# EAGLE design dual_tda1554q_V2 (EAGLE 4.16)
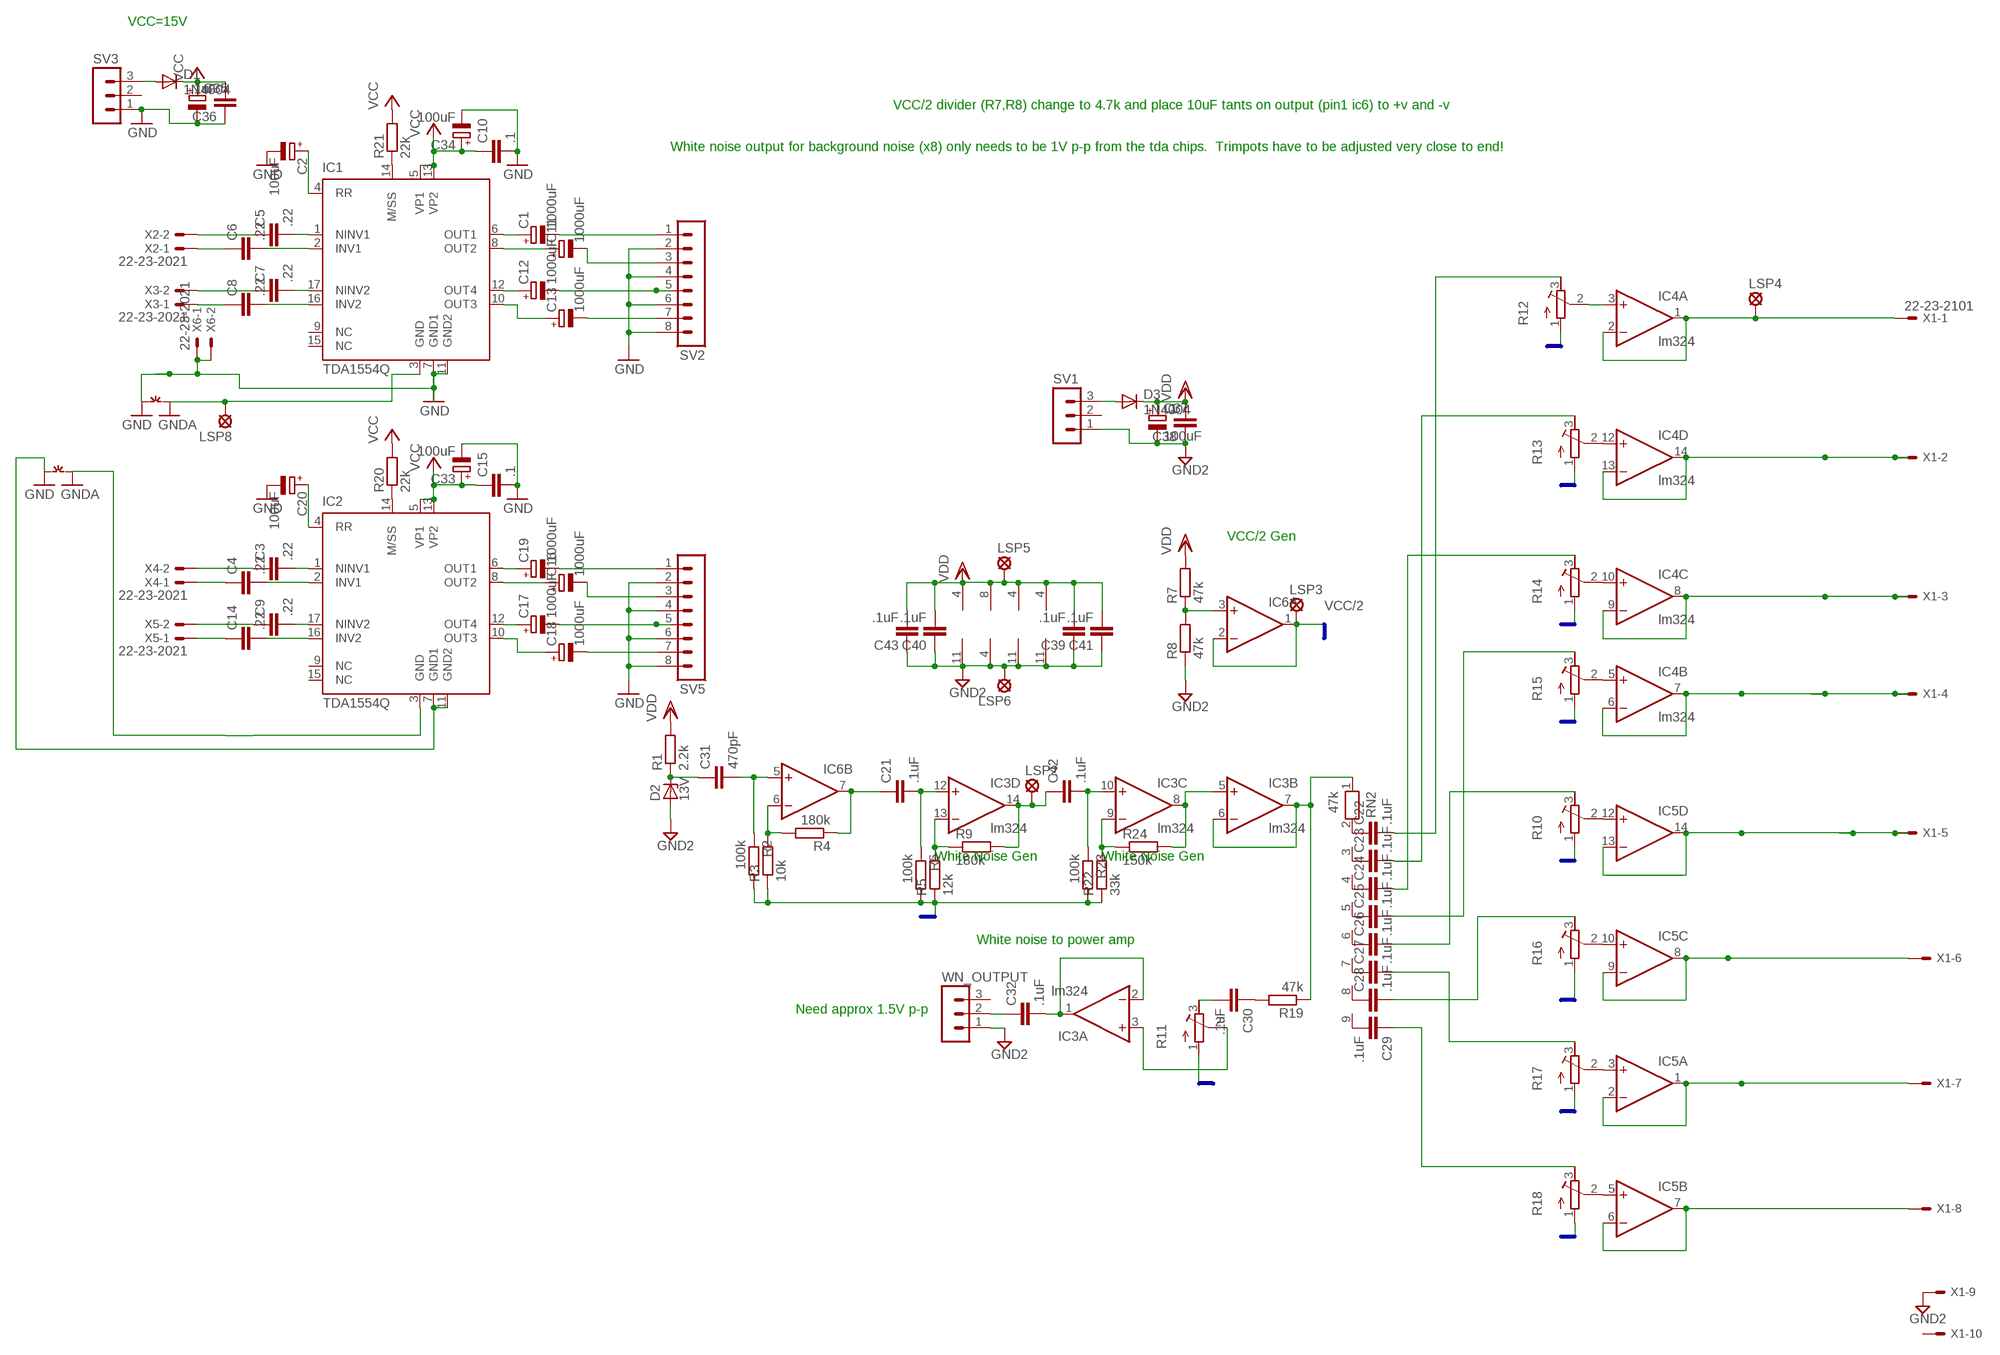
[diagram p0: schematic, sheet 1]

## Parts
C1  1000uF  CPOL-EUE5-10.5  [E5-10,5]
C2  100uF  CPOL-EUE5-6  [E5-6]
C3  .22  C-EU025-025X050  [C025-025X050]
C4  .22  C-EU025-025X050  [C025-025X050]
C5  .22  C-EU025-025X050  [C025-025X050]
C6  .22  C-EU025-025X050  [C025-025X050]
C7  .22  C-EU025-025X050  [C025-025X050]
C8  .22  C-EU025-025X050  [C025-025X050]
C9  .22  C-EU025-025X050  [C025-025X050]
C10  .1  C-EU025-025X050  [C025-025X050]
C11  1000uF  CPOL-EUE5-10.5  [E5-10,5]
C12  1000uF  CPOL-EUE5-10.5  [E5-10,5]
C13  1000uF  CPOL-EUE5-10.5  [E5-10,5]
C14  .22  C-EU025-025X050  [C025-025X050]
C15  .1  C-EU025-025X050  [C025-025X050]
C16  1000uF  CPOL-EUE5-10.5  [E5-10,5]
C17  1000uF  CPOL-EUE5-10.5  [E5-10,5]
C18  1000uF  CPOL-EUE5-10.5  [E5-10,5]
C19  1000uF  CPOL-EUE5-10.5  [E5-10,5]
C20  100uF  CPOL-EUE5-6  [E5-6]
C21  .1uF  C-EU025-025X050  [C025-025X050]
C22  .1uF  C-EU025-025X050  [C025-025X050]
C23  .1uF  C-EU025-025X050  [C025-025X050]
C24  .1uF  C-EU025-025X050  [C025-025X050]
C25  .1uF  C-EU025-025X050  [C025-025X050]
C26  .1uF  C-EU025-025X050  [C025-025X050]
C27  .1uF  C-EU025-025X050  [C025-025X050]
C28  .1uF  C-EU025-025X050  [C025-025X050]
C29  .1uF  C-EU025-025X050  [C025-025X050]
C30  .1uF  C-EU025-025X050  [C025-025X050]
C31  470pF  C-EU025-025X050  [C025-025X050]
C32  .1uF  C-EU025-025X050  [C025-025X050]
C33  100uF  CPOL-EUE5-6  [E5-6]
C34  100uF  CPOL-EUE5-6  [E5-6]
C35  CPOL-EUE7.5-16  [E7,5-16]
C36  .1uF  C-EUC1206  [C1206]
C37  100uF  CPOL-EUE5-8.5  [E5-8,5]
C38  .1  C-EU025-025X050  [C025-025X050]
C39  .1uF  C-EUC1206  [C1206]
C40  .1uF  C-EUC1206  [C1206]
C41  .1uF  C-EUC1206  [C1206]
C42  .1uF  C-EU025-025X050  [C025-025X050]
C43  .1uF  C-EU025-025X050  [C025-025X050]
D1  1N4004  [DO41-10]
D2  13V  ZENER-DIODEF126-10  [F126Z10]
D3  1N4004  [DO41-10]
IC1  TDA1554Q  [MULTIWAT-SIL17]
IC2  TDA1554Q  [MULTIWAT-SIL17]
IC3  lm324  4AMP_P4+11N  [DIL14]
IC4  lm324  4AMP_P4+11N  [DIL14]
IC5  4AMP_P4+11N  [DIL14]
IC6  2AMP_P8+4N  [DIL08]
LSP2  SE14  [SE14]
LSP3  SE14  [SE14]
LSP4  SE14  [SE14]
LSP5  SE14  [SE14]
LSP6  SE14  [SE14]
LSP8  SE14  [SE14]
R1  2.2k  R-EU_0204/2V  [0204V]
R2  100k  R-EU_0204/7  [0204/7]
R3  10k  R-EU_0204/2V  [0204V]
R4  180k  R-EU_0204/2V  [0204V]
R5  12k  R-EU_0204/5  [0204/5]
R6  100k  R-EU_0204/7  [0204/7]
R7  47k  R-EU_0204/2V  [0204V]
R8  47k  R-EU_0204/2V  [0204V]
R9  180k  R-EU_0204/2V  [0204V]
R10  R-TRIMM64Y  [RTRIM64Y]
R11  R-TRIMM64Y  [RTRIM64Y]
R12  R-TRIMM64Y  [RTRIM64Y]
R13  R-TRIMM64Y  [RTRIM64Y]
R14  R-TRIMM64Y  [RTRIM64Y]
R15  R-TRIMM64Y  [RTRIM64Y]
R16  R-TRIMM64Y  [RTRIM64Y]
R17  R-TRIMM64Y  [RTRIM64Y]
R18  R-TRIMM64Y  [RTRIM64Y]
R19  47k  R-EU_0204/2V  [0204V]
R20  22k  R-EU_0204/2V  [0204V]
R21  22k  R-EU_0204/2V  [0204V]
R22  33k  R-EU_0204/7  [0204/7]
R23  100k  R-EU_0204/5  [0204/5]
R24  150k  R-EU_0204/2V  [0204V]
RN2  47k  RN08  [RN-9]
SV1  MA03-1  [MA03-1]
SV2  MA08-1  [MA08-1]
SV3  MA03-1  [MA03-1]
SV5  MA08-1  [MA08-1]
WN_OUTPUT  MA03-1  [MA03-1]
X1  22-23-2101  [22-23-2101]
X2  22-23-2021  [22-23-2021]
X3  22-23-2021  [22-23-2021]
X4  22-23-2021  [22-23-2021]
X5  22-23-2021  [22-23-2021]
X6  22-23-2021  [22-23-2021]
~NUDEV~1  GND-GNDA  [GND-GNDA]
~NUDEV~2  GND-GNDA  [GND-GNDA]

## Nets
A1 [AF_OUT]: C1.- SV2.1
A2 [AF_OUT]: C11.- SV2.3
A3 [AF_OUT]: C12.- SV2.5
A4 [AF_OUT]: C13.- SV2.7
A5 [AF_OUT]: C19.- SV5.1
A6 [AF_OUT]: C16.- SV5.3
A7 [AF_OUT]: C17.- SV5.5
A8 [AF_OUT]: C18.- SV5.7
GND [power]: C2.- C10.2 C15.2 C20.- C33.- C34.- C35.- C36.1 IC1.7(GND1) IC1.11(GND2) IC2.7(GND1) IC2.11(GND2) SV2.2 SV2.4 SV2.6 SV2.8 SV3.1 SV5.2 SV5.4 SV5.6 SV5.8 X6.1 X6.2 ~NUDEV~1.GND ~NUDEV~2.GND
GND2 [power]: C37.- C38.1 C39.1 C40.1 C41.1 C43.1 D2.A IC3.11(P:V-) IC4.11(P:V-) IC5.11(P:V-) IC6.4(P:V-) LSP6.MP R8.1 SV1.1 WN_OUTPUT.1 X1.9
GNDA [SIG_GND]: IC1.3(GND) IC2.3(GND) LSP8.MP ~NUDEV~1.GNDA ~NUDEV~2.GNDA
INV1: C6.2 IC1.2(INV1)
INV2: C8.2 IC1.16(INV2)
INV3: C14.2 IC2.16(INV2)
N$1 [AF_OUT]: C13.+ IC1.10(OUT3)
N$2: IC2.14(M/SS) R20.1
N$3 [AF_OUT]: C12.+ IC1.12(OUT4)
N$4: IC1.14(M/SS) R21.1
N$5 [AF_OUT]: C11.+ IC1.8(OUT2)
N$6 [power]: D3.A SV1.3
N$7: C3.2 IC2.1(NINV1)
N$8: C2.+ IC1.4(RR)
N$9 [AF_OUT]: C1.+ IC1.6(OUT1)
N$10: C27.2 R17.3(A)
N$11: C31.2 IC6.5(B:+IN) R2.1
N$12 [SIG_GND]: C3.1 X4.2
N$13: C9.1 X5.2
N$14 [power]: D1.A SV3.3
N$15: C14.1 X5.1
N$16: C5.1 X2.2
N$17: C6.1 X2.1
N$18: C7.1 X3.2
N$19 [AF_OUT]: C18.+ IC2.10(OUT3)
N$20: C8.1 X3.1
N$21 [AF_OUT]: C17.+ IC2.12(OUT4)
N$22 [AF_OUT]: C16.+ IC2.8(OUT2)
N$23: C42.1 IC3.14(D:OUT) LSP2.MP R9.2
N$24: C42.2 IC3.10(C:+IN) R23.1
N$25: C20.+ IC2.4(RR)
N$26 [AF_OUT]: C19.+ IC2.6(OUT1)
N$27: IC3.9(C:-IN) R22.2 R24.1
N$28: C31.1 D2.C R1.1
N$29: IC6.6(B:-IN) R3.2 R4.2
N$30: IC6.3(A:+IN) R7.1 R8.2
N$31: C21.2 IC3.12(D:+IN) R6.1
N$32: C29.2 RN2.9
N$33: IC3.13(D:-IN) R5.2 R9.1
N$34: C29.1 R18.3(A)
N$35: C21.1 IC6.7(B:OUT) R4.1
N$36: C30.1 R19.2
N$37: C28.2 R16.3(A)
N$38: C26.2 R10.3(A)
N$39: C25.2 R15.3(A)
N$40: C24.2 R14.3(A)
N$41: C23.2 R13.3(A)
N$42: C22.2 R12.3(A)
N$43: C22.1 RN2.2
N$44: C23.1 RN2.3
N$45: C24.1 RN2.4
N$46: C25.1 RN2.5
N$47: C26.1 RN2.6
N$48: C32.1 WN_OUTPUT.2
N$49: IC4.3(A:+IN) R12.2(S)
N$50: C27.1 RN2.7
N$51: IC5.12(D:+IN) R10.2(S)
N$52: IC5.10(C:+IN) R16.2(S)
N$53: IC4.12(D:+IN) R13.2(S)
N$54: C28.1 RN2.8
N$55: IC4.10(C:+IN) R14.2(S)
N$56: C4.2 IC2.2(INV1)
N$57 [SIG_GND]: C4.1 X4.1
N$58: IC5.3(A:+IN) R17.2(S)
N$59: IC5.5(B:+IN) R18.2(S)
N$60: IC3.5(B:+IN) IC3.8(C:OUT) R24.2
N$61: C30.2 R11.3(A)
N$62: IC3.6(B:-IN) IC3.7(B:OUT) R19.1 RN2.1
N$72: IC4.5(B:+IN) R15.2(S)
NINV1: C5.2 IC1.1(NINV1)
NINV2: C7.2 IC1.17(NINV2)
NINV3: C9.2 IC2.17(NINV2)
VCC [power]: C10.1 C15.1 C33.+ C34.+ C35.+ C36.2 D1.C IC1.5(VP1) IC1.13(VP2) IC2.5(VP1) IC2.13(VP2) R20.2 R21.2
VCC/2 [vcc/2]: IC6.1(A:OUT) IC6.2(A:-IN) LSP3.MP R2.2 R3.1 R5.1 R6.2 R10.1(E) R11.1(E) R12.1(E) R13.1(E) R14.1(E) R15.1(E) R16.1(E) R17.1(E) R18.1(E) R22.1 R23.2
VDD [power]: C37.+ C38.2 C39.2 C40.2 C41.2 C43.2 D3.C IC3.4(P:V+) IC4.4(P:V+) IC5.4(P:V+) IC6.8(P:V+) LSP5.MP R1.2 R7.2
WN1: IC4.1(A:OUT) IC4.2(A:-IN) LSP4.MP X1.1
WN2: IC4.13(D:-IN) IC4.14(D:OUT) X1.2
WN3: IC4.8(C:OUT) IC4.9(C:-IN) X1.3
WN4: IC4.6(B:-IN) IC4.7(B:OUT) X1.4
WN5: IC5.13(D:-IN) IC5.14(D:OUT) X1.5
WN6: IC5.1(A:OUT) IC5.2(A:-IN) X1.7
WN7: IC5.8(C:OUT) IC5.9(C:-IN) X1.6
WN8: IC5.6(B:-IN) IC5.7(B:OUT) X1.8
WN+: IC3.3(A:+IN) R11.2(S)
WN_FEEDBACK: C32.2 IC3.1(A:OUT) IC3.2(A:-IN)
Unconnected: IC1.9(NC) IC1.15(NC) IC2.9(NC) IC2.15(NC) SV1.2 SV3.2 WN_OUTPUT.3 X1.10

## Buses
VCC/2

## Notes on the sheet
- VCC=15V
- VCC/2 divider (R7,R8) change to 4.7k and place 10uF tants on output (pin1 ic6) to +v and -v
- White noise output for background noise (x8) only needs to be 1V p-p from the tda chips.  Trimpots have to be adjusted very close to end!
- VCC/2 Gen
- White Noise Gen | White Noise Gen
- White noise to power amp
- Need approx 1.5V p-p

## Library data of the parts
C1 C2 C11-C13 C16-C20 C33-C35 C37 = rcl:CPOL-EU: POLARIZED CAPACITOR, European symbol
C3-C10 C14 C15 C21-C32 C36 C38-C43 = rcl:C-EU: CAPACITOR, European symbol
D1 D3 = diode:1N4004: DIODE
D2 = diode:ZENER-DIODE: Z-Diode
IC1 IC2 = linear2:TDA1554Q: Audio Power Amplifier 4x11W single-ended or 2x22W BTL source: TDA1554Q_CNV.pdf
IC3-IC5 = linear:4AMP_P4+11: OP AMP
IC6 = linear:2AMP_P8+4: OP AMP
LSP2-LSP6 LSP8 = solpad:SE14: SOLDER PAD
R1-R9 R19-R24 = rcl:R-EU_: RESISTOR, European symbol
R10-R18 = rcl:R-TRIMM: Trimm resistor
RN2 = resistor-net:RN08: RESISTOR NETWORK
SV1 SV3 WN_OUTPUT = con-lstb:MA03-1: PIN HEADER
SV2 SV5 = con-lstb:MA08-1: PIN HEADER
X1 = con-molex:22-23-2101: .100" (2.54mm) Center Header - 10 Pin
X2-X6 = con-molex:22-23-2021: .100" (2.54mm) Center Header - 2 Pin
~NUDEV~1 ~NUDEV~2 = supply-dummy:GND-GNDA: Example of GND--GNDA NET-Connetor for more info read description in package

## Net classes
0 default: width 0.254 mm, drill 0.254 mm, clearance 0.711 mm
1 power: width 1.016 mm, drill 0.61 mm, clearance 0.711 mm
2 vcc/2: width 0.508 mm, drill 0.254 mm, clearance 0.711 mm
3 AF_OUT: width 0.508 mm, drill 0.254 mm, clearance 0.711 mm
4 SIG_GND: width 0.508 mm, drill 0.254 mm, clearance 0.711 mm

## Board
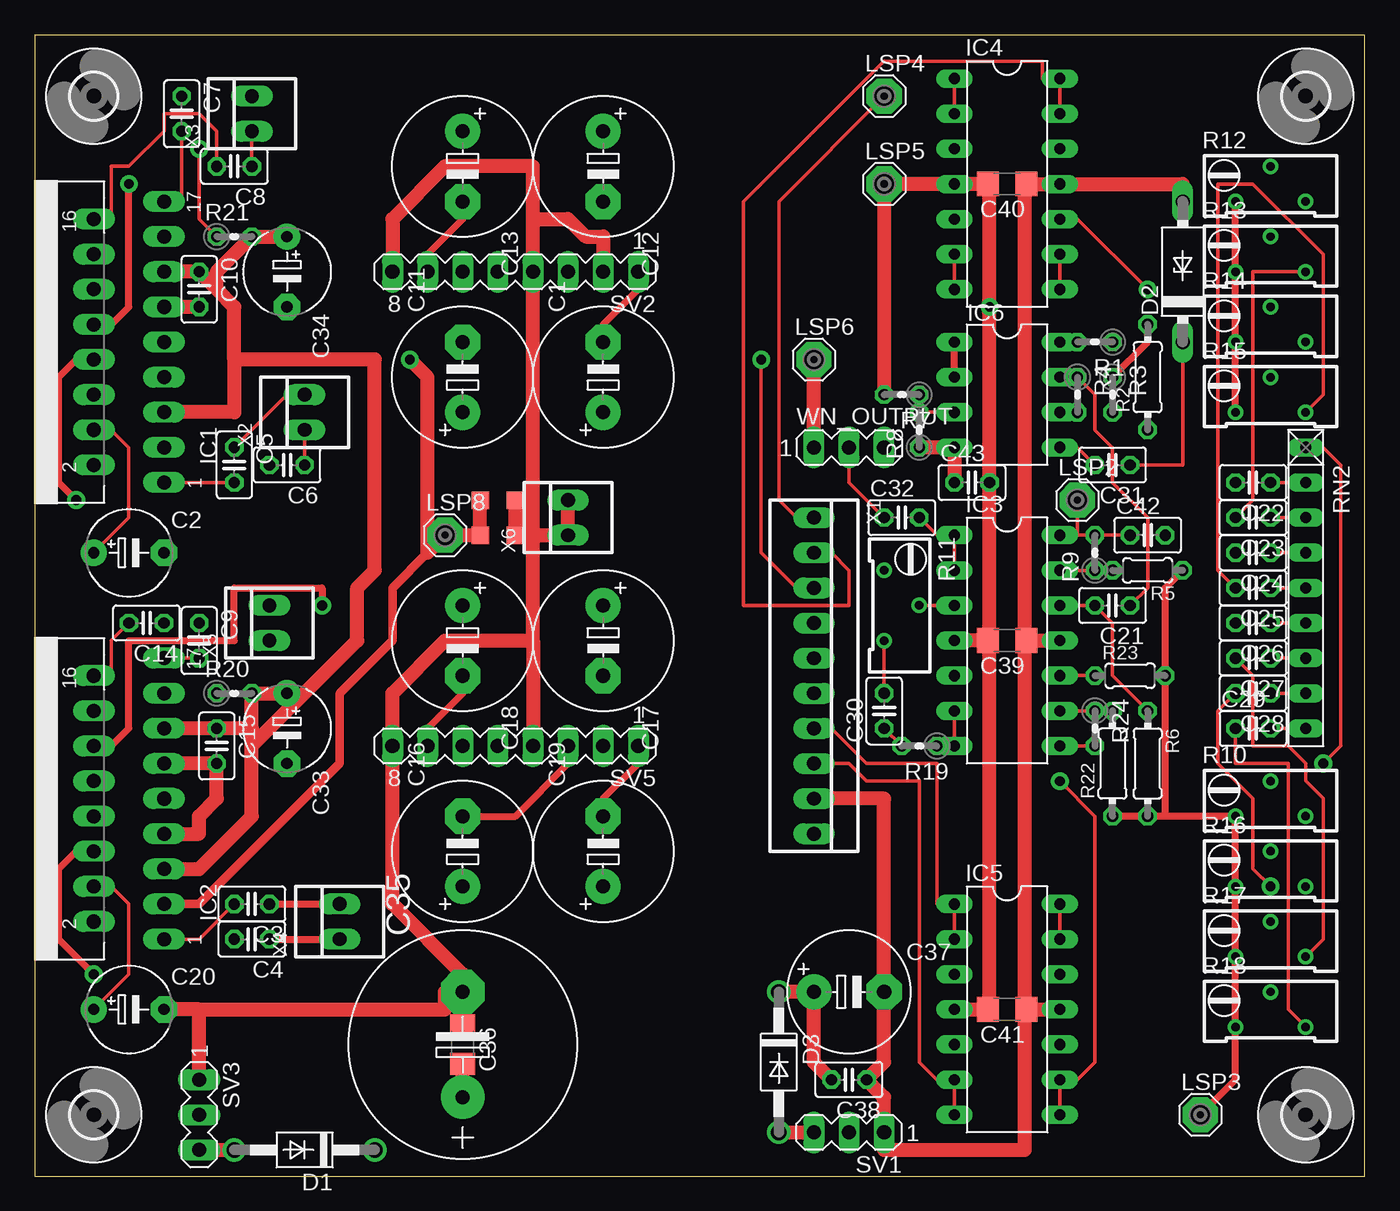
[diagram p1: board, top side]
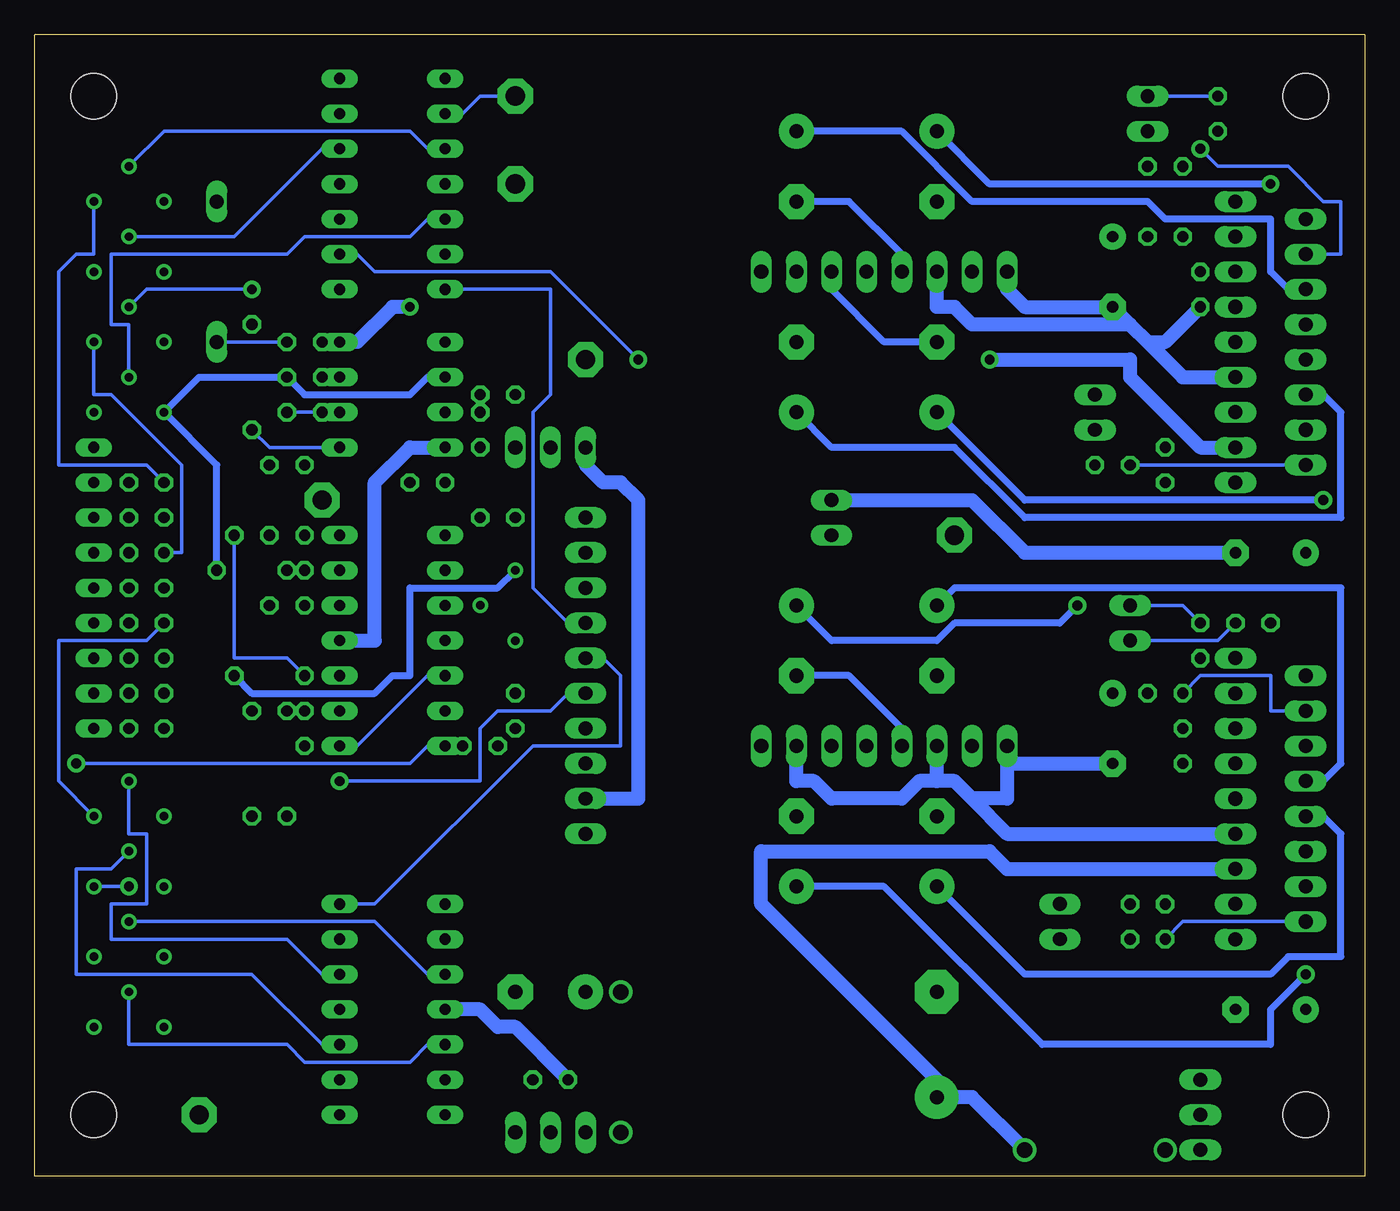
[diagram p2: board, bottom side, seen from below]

Size 96.19 x 82.55 mm. Coordinates in mm from the lower left corner, seen from the top.
Outline: 96.19,82.54 96.19,0 0,0 0,82.54
Outline: 0,82.55 96.19,82.55
Copper layers (1*16): Top 0.035mm / dielectric 1.5mm / Bottom 0.035mm
Design rules "futurlec": minimum track width 10mil, minimum drill 24mil, track to track 10mil, track to pad 10mil, pad to pad 10mil, via to via 10mil, smd to smd 0mil, copper to edge 40mil, drill to drill 10mil, minimum pad ring 10mil, minimum via ring 8mil, stop-mask expansion 4mil, vias tented up to drill 0mil, thermal gap 10mil
tRestrict: area 18.2,76.8 to 19.5,79.4; area 20.8,54 to 22.1,56.5; area 18.2,38.7 to 19.5,41.3; area 15.7,36.2 to 18.2,37.5; area 23.3,17.1 to 24.6,19.7; area 46.2,1.9 to 50,80.6
bRestrict: area 18.2,38.7 to 19.5,41.3; area 20.8,54 to 22.1,56.5; area 18.2,76.8 to 19.5,79.4; area 15.7,36.2 to 18.2,37.5; area 23.3,17.1 to 24.6,19.7; area 46.2,1.9 to 50,80.6

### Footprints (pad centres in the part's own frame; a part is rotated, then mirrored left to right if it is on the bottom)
E5-10,5 = drill 1.016 pad 2.54 round: + -2.54,0 | drill 1.016 pad 2.54 octagon: - 2.54,0
E5-6 = drill 0.813 pad 1.905 round: + -2.54,0 | drill 0.813 pad 1.905 octagon: - 2.54,0
C025-025X050 = drill 0.813 octagon: 1 -1.27,0; 2 1.27,0
E7,5-16 = drill 1.016 pad 3.15 round: + -3.81,0 | drill 1.016 pad 3.15 octagon: - 3.81,0
C1206 = smd 1.6 x 1.8: 1 -1.4,0; 2 1.4,0
E5-8,5 = drill 1.016 pad 2.54 round: + -2.54,0 | drill 1.016 pad 2.54 octagon: - 2.54,0
DO41-10 = drill 1.118 round: A 5.08,0; C -5.08,0
F126Z10 = drill 1.016 long: A 5.08,0; C -5.08,0
MULTIWAT-SIL17 = drill 1.016 long: 1 -10.16,-7.62; 2 -8.89,-2.54; 3 -7.62,-7.62; 4 -6.35,-2.54; 5 -5.08,-7.62; 6 -3.81,-2.54; 7 -2.54,-7.62; 8 -1.27,-2.54; 9 0,-7.62; 10 1.27,-2.54; 11 2.54,-7.62; 12 3.81,-2.54; 13 5.08,-7.62; 14 6.35,-2.54; 15 7.62,-7.62; 16 8.89,-2.54; 17 10.16,-7.62
DIL14 = drill 0.813 long: 1 -7.62,-3.81; 2 -5.08,-3.81; 3 -2.54,-3.81; 4 0,-3.81; 5 2.54,-3.81; 6 5.08,-3.81; 7 7.62,-3.81; 8 7.62,3.81; 9 5.08,3.81; 10 2.54,3.81; 11 0,3.81; 12 -2.54,3.81; 13 -5.08,3.81; 14 -7.62,3.81
DIL08 = drill 0.813 long: 1 -3.81,-3.81; 2 -1.27,-3.81; 3 1.27,-3.81; 4 3.81,-3.81; 5 3.81,3.81; 6 1.27,3.81; 7 -1.27,3.81; 8 -3.81,3.81
SE14 = drill 1.397 pad 2.54 octagon: MP 0,0
0204V = drill 0.813 octagon: 1 -1.27,0; 2 1.27,0
0204/7 = drill 0.813 octagon: 1 -3.81,0; 2 3.81,0
0204/5 = drill 0.813 octagon: 1 -2.54,0; 2 2.54,0
RTRIM64Y = drill 0.61 round: 1 0,-2.54; 2 -2.54,0; 3 0,2.54
RN-9 = drill 0.813 long: 1 -10.16,0; 2 -7.62,0; 3 -5.08,0; 4 -2.54,0; 5 0,0; 6 2.54,0; 7 5.08,0; 8 7.62,0; 9 10.16,0
MA03-1 = drill 1.016 long: 1 -2.54,0; 2 0,0; 3 2.54,0
MA08-1 = drill 1.016 long: 1 -8.89,0; 2 -6.35,0; 3 -3.81,0; 4 -1.27,0; 5 1.27,0; 6 3.81,0; 7 6.35,0; 8 8.89,0
3,3 = hole 3.3: 0,0
22-23-2101 = drill 1 long: 1 -11.43,0; 2 -8.89,0; 3 -6.35,0; 4 -3.81,0; 5 -1.27,0; 6 1.27,0; 7 3.81,0; 8 6.35,0; 9 8.89,0; 10 11.43,0
22-23-2021 = drill 1 long: 1 -1.27,0; 2 1.27,0
GND-GNDA = smd 1.27 x 1.27: GND -1.27,0; GNDA 1.27,0

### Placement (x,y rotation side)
C1  41.11,57.78 90 top
C2  6.82,45.08 0 top
C3  15.71,19.68 180 top
C4  15.71,17.14 180 top
C5  14.44,51.43 270 top
C6  18.25,51.43 180 top
C7  10.63,76.83 270 top
C8  14.44,73.02 180 top
C9  11.9,38.73 270 top
C10  11.9,64.13 270 top
C11  30.95,57.78 90 top
C12  41.11,73.02 270 top
C13  30.95,73.02 270 top
C14  8.09,40 180 top
C15  13.17,31.11 270 top
C16  30.95,23.49 90 top
C17  41.11,38.73 270 top
C18  30.95,38.73 270 top
C19  41.11,23.49 90 top
C20  6.82,12.06 0 top
C21  77.94,41.27 180 top
C22  88.1,50.16 180 top
C23  88.1,47.62 180 top
C24  88.1,45.08 180 top
C25  88.1,42.54 180 top
C26  88.1,40 180 top
C27  88.1,37.46 180 top
C28  88.1,34.92 180 top
C29  88.1,32.38 0 top
C30  61.43,33.65 90 top
C31  77.94,51.43 180 top
C32  62.7,47.62 0 top
C33  18.25,32.38 270 top
C34  18.25,65.4 270 top
C35  30.95,9.52 90 top
C36  30.95,9.52 270 top
C37  58.89,13.33 0 top
C38  58.89,6.98 180 top
C39  70.32,38.73 180 top
C40  70.32,71.75 180 top
C41  70.32,12.06 180 top
C42  80.48,46.35 0 top
C43  67.78,50.16 0 top
D1  19.52,1.9 180 top
D2  83.02,65.4 90 top
D3  53.81,8.25 270 top
IC1  1.74,60.32 90 top
IC2  1.74,27.3 90 top
IC3  70.32,38.73 270 top
IC4  70.32,71.75 270 top
IC5  70.32,12.06 270 top
IC6  70.32,56.51 270 top
LSP2  75.4,48.89 0 top
LSP3  84.29,4.44 0 top
LSP4  61.43,78.1 0 top
LSP5  61.43,71.75 0 top
LSP6  56.35,59.05 0 top
LSP8  29.68,46.35 0 top
R1  76.67,60.32 180 top
R2  80.48,57.78 90 top
R3  77.94,56.51 270 top
R4  75.4,56.51 270 top
R5  80.48,43.81 180 top
R6  80.48,29.84 270 top
R7  62.7,56.51 180 top
R8  63.97,53.97 90 top
R9  76.67,45.08 90 top
R10  89.37,26.03 270 top
R11  61.43,41.27 180 top
R12  89.37,70.48 270 top
R13  89.37,65.4 270 top
R14  89.37,60.32 270 top
R15  89.37,55.24 270 top
R16  89.37,20.95 270 top
R17  89.37,15.87 270 top
R18  89.37,10.79 270 top
R19  63.97,31.11 180 top
R20  14.44,34.92 0 top
R21  14.44,67.94 0 top
R22  77.94,29.84 90 top
R23  79.21,36.19 0 top
R24  76.67,32.38 270 top
RN2  91.91,42.54 270 top
SV1  58.89,3.17 180 top
SV2  34.76,65.4 180 top
SV3  11.9,4.44 270 top
SV5  34.76,31.11 180 top
U$1  [3,3]  4.28,78.1 0 top
U$2  [3,3]  91.91,78.1 0 top
U$3  [3,3]  91.91,4.44 0 top
U$4  [3,3]  4.28,4.44 0 top
WN_OUTPUT  58.89,52.7 0 top
X1  56.35,36.19 270 top
X2  19.52,55.24 90 top
X3  15.71,76.83 90 top
X4  22.06,18.41 90 top
X5  16.98,40 90 top
X6  38.57,47.62 90 top
~NUDEV~1  33.49,46.35 180 top
~NUDEV~2  33.49,48.89 180 top

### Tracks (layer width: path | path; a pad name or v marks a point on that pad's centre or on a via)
A1
  Top 0.508: C1.- 41.11,61.59 43.65,64.13 SV2.1
A2
  Bottom 0.508: C11.- 34.76,60.32 38.57,64.13 SV2.3
A3
  Bottom 0.508: C12.- 37.3,70.48 33.49,66.67 SV2.5
A4
  Top 0.508: C13.- 30.95,69.21 28.41,66.67 SV2.7
A5
  Top 0.508: C19.- 41.11,27.3 43.65,29.84 SV5.1
A6
  Top 0.508: C16.- 34.76,26.03 38.57,29.84 SV5.3
A7
  Bottom 0.508: C17.- 37.3,36.19 33.49,32.38 SV5.5
A8
  Top 0.508: C18.- 30.95,34.92 28.41,32.38 SV5.7
GND
  Top 1.016: 30.95,10.79 C36.1 C35.- | 11.9,12.06 C20.- | 11.9,12.06 29.68,12.06 29.68,13.33 C35.- | IC2.11 C15.2 13.17,27.3 11.9,26.03 11.9,24.76 IC2.7 | C35.- 30.95,14.6 25.87,19.68 SV5.8 25.87,34.92 29.68,38.73 36.03,38.73 | C10.2 IC1.11 | ~NUDEV~2.GND ~NUDEV~1.GND 36.03,46.35 | 36.03,46.35 X6.1 X6.2 | 36.03,38.73 36.03,46.35 | 36.03,38.73 SV5.4 | 36.03,46.35 SV2.4 36.03,69.21 | 36.03,69.21 38.57,69.21 39.84,67.94 41.11,67.94 SV2.2 | 36.03,69.21 36.03,73.02 29.68,73.02 25.87,69.21 SV2.8 | SV3.1 11.9,12.06
  Bottom 1.016: 25.87,29.84 C33.- | 30.95,28.57 29.68,28.57 28.41,27.3 | 28.41,27.3 25.87,24.76 IC2.7 | 30.95,28.57 SV5.6 | 30.95,28.57 32.22,28.57 33.49,27.3 38.57,27.3 39.84,28.57 41.11,28.57 SV5.2 | 25.87,29.84 25.87,27.3 28.41,27.3 | SV5.8 25.87,29.84 | 16.98,61.59 C34.- 24.6,62.86 25.87,64.13 SV2.8 | 16.98,61.59 15.71,60.32 | 15.71,60.32 13.17,57.78 IC1.7 | C10.2 14.44,60.32 15.71,60.32 | C2.- 24.6,45.08 28.41,48.89 X6.2 | 16.98,61.59 28.41,61.59 29.68,62.86 30.95,62.86 SV2.6
GND2
  Top 1.016: WN_OUTPUT.1 LSP6.MP | X1.9 61.43,27.3 C37.- 61.43,8.25 C38.1 61.43,5.71 SV1.1 61.43,1.9 71.59,1.9 71.59,12.06 | D2.A 83.02,71.75 IC4.11 C40.1 71.59,71.75 71.59,38.73 | C43.1 IC6.4 R8.1 | IC5.11 C41.1 71.59,12.06 | IC3.11 C39.1 71.59,38.73 | 71.59,12.06 71.59,38.73
  Bottom 1.016: WN_OUTPUT.1 56.35,51.43 55.08,50.16 53.81,50.16 52.54,48.89 52.54,27.3 X1.9 | IC6.4 69.05,52.7 71.59,50.16 71.59,38.73 IC3.11
GNDA  (via drill 0.71)
  Top 0.61: 28.41,45.08 25.87,42.54 25.87,38.73 22.06,34.92 22.06,29.84 11.9,19.68 IC2.3
  Top 1.016: ~NUDEV~2.GNDA ~NUDEV~1.GNDA LSP8.MP 28.41,45.08 28.41,57.78 v27.14,59.05
  Bottom 1.016: v27.14,59.05 16.98,59.05 16.98,57.78 11.9,52.7 IC1.3
INV1
  Bottom 0.254: IC1.2 C6.2
INV2
  Top 0.254: C8.2 13.17,75.56 11.9,76.83 9.36,76.83 9.36,75.56 6.82,73.02 5.55,73.02 5.55,69.21 IC1.16
INV3
  Top 0.254: C14.2 5.55,38.73 5.55,36.19 IC2.16
N$1  (via drill 0.71)
  Top 0.508: v6.82,71.75 6.82,62.86 5.55,61.59 IC1.10
  Bottom 0.508: v6.82,71.75 27.14,71.75 C13.+
N$2
  Bottom 0.254: R20.1 11.9,36.19 6.82,36.19 6.82,33.65 IC2.14
N$3
  Bottom 0.508: C12.+ 33.49,75.56 28.41,70.48 15.71,70.48 14.44,69.21 6.82,69.21 6.82,65.4 5.55,64.13 IC1.12
N$4  (via drill 0.71)
  Top 0.254: R21.1 11.9,69.21 v11.9,74.29
  Bottom 0.254: v11.9,74.29 10.63,73.02 5.55,73.02 3.01,70.48 1.74,70.48 1.74,66.67 IC1.14
N$5  (via drill 0.71)
  Top 0.508: v3.01,48.89 1.74,50.16 1.74,57.78 3.01,59.05 IC1.8
  Bottom 0.508: v3.01,48.89 24.6,48.89 C11.+
N$6
  Top 1.016: D3.A SV1.3
N$7
  Top 0.254: C3.2 11.9,17.14 IC2.1
N$8
  Top 0.254: C2.+ 6.82,47.62 6.82,52.7 5.55,53.97 IC1.4
N$9
  Bottom 0.508: C1.+ 38.57,52.7 29.68,52.7 24.6,47.62 1.74,47.62 1.74,55.24 3.01,56.51 IC1.6
N$10
  Top 0.254: R17.3 93.18,17.14 93.18,27.3 91.91,28.57 91.91,29.84 90.64,31.11 88.1,31.11 88.1,36.19 C27.2
N$11
  Top 0.254: C31.2 75.4,52.7 IC6.5
  Bottom 0.254: R2.1 79.21,52.7 IC6.5
N$12
  Top 0.508: C3.1 X4.2
N$13
  Bottom 0.254: C9.1 13.17,41.27 X5.2
N$14
  Top 1.016: SV3.3 D1.A
N$15
  Bottom 0.254: C14.1 10.63,38.73 X5.1
N$16
  Top 0.254: C5.1 18.25,56.51 X2.2
N$17
  Top 0.254: C6.1 X2.1
N$18
  Bottom 0.254: C7.1 X3.2
N$19
  Bottom 0.508: C18.+ 29.68,42.54 1.74,42.54 1.74,29.84 3.01,28.57 IC2.10
N$20
  Top 0.254: C8.1 X3.1
N$21  (via drill 0.71)
  Top 0.508: v20.79,41.27 20.79,42.54 14.44,42.54 14.44,38.73 6.82,38.73 6.82,32.38 5.55,31.11 IC2.12
  Bottom 0.508: v20.79,41.27 22.06,40 29.68,40 30.95,38.73 38.57,38.73 C17.+
N$22
  Bottom 0.508: C16.+ 24.6,14.6 6.82,14.6 5.55,15.87 1.74,15.87 1.74,24.76 3.01,26.03 IC2.8
N$23
  Top 0.254: 75.4,46.35 R9.2 C42.1 | 75.4,46.35 LSP2.MP | IC3.14 75.4,46.35
N$24
  Top 0.254: IC3.10 R23.1
  Bottom 0.254: C42.2 81.75,37.46 77.94,37.46 R23.1
N$25
  Top 0.254: C20.+ 6.82,14.6 6.82,19.68 5.55,20.95 IC2.4
N$26  (via drill 0.71)
  Top 0.508: v4.28,14.6 1.74,17.14 1.74,22.22 3.01,23.49 IC2.6
  Bottom 0.508: v4.28,14.6 6.82,12.06 6.82,9.52 23.33,9.52 34.76,20.95 C19.+
N$27
  Top 0.254: IC3.9 R24.1 R22.2
N$28
  Top 0.254: C31.1 83.02,51.43 D2.C
  Bottom 0.254: D2.C R1.1
N$29
  Top 0.254: IC6.6 R4.2
  Bottom 0.254: R3.2 R4.2 IC6.6
N$30
  Top 0.254: R7.1 R8.2 IC6.3
N$31
  Top 0.254: IC3.12 C21.2 77.94,40 77.94,36.19 R6.1
N$32
  Top 0.254: C29.2 RN2.9
N$33
  Top 0.254: IC3.13 R9.1 R5.2
N$34
  Top 0.254: R18.3 90.64,12.06 90.64,29.84 86.83,29.84 C29.1
N$35
  Top 0.254: R4.1 IC6.7 R4.1 | C21.1 80.48,42.54 80.48,47.62 77.94,50.16 77.94,52.7 76.67,53.97 76.67,56.51 R4.1
N$36
  Top 0.254: R19.2 C30.1
N$37  (via drill 0.71)
  Top 0.254: v89.37,20.95 88.1,22.22 88.1,27.3 85.56,29.84 85.56,33.65 C28.2
  Bottom 0.254: v89.37,20.95 R16.3
N$38
  Bottom 0.254: R10.3 94.45,28.57 94.45,38.73 88.1,38.73 C26.2
N$39
  Top 0.254: R15.3 93.18,56.51 93.18,66.67 88.1,71.75 85.56,71.75 85.56,43.81 C25.2
N$40
  Bottom 0.254: R14.3 91.91,56.51 90.64,56.51 85.56,51.43 85.56,45.08 C24.2
N$41
  Top 0.254: R13.3 88.1,65.4 88.1,48.89 C23.2
N$42
  Bottom 0.254: R12.3 91.91,66.67 93.18,66.67 94.45,65.4 94.45,51.43 88.1,51.43 C22.2
N$43
  Top 0.254: C22.1 RN2.2
N$44
  Top 0.254: C23.1 RN2.3
N$45
  Top 0.254: C24.1 RN2.4
N$46
  Top 0.254: C25.1 RN2.5
N$47
  Top 0.254: C26.1 RN2.6
N$48
  Top 0.254: C32.1 58.89,50.16 WN_OUTPUT.2
N$49
  Bottom 0.254: R12.2 86.83,75.56 69.05,75.56 67.78,74.29 IC4.3
N$50
  Top 0.254: C27.1 RN2.7
N$51
  Bottom 0.254: R10.2 89.37,24.76 88.1,24.76 88.1,19.68 90.64,19.68 90.64,17.14 77.94,17.14 75.4,14.6 IC5.12
N$52
  Bottom 0.254: R16.2 90.64,22.22 93.18,22.22 93.18,14.6 80.48,14.6 75.4,9.52 IC5.10
N$53
  Bottom 0.254: R13.2 81.75,67.94 75.4,74.29 IC4.12
N$54
  Top 0.254: C28.1 RN2.8
N$55  (via drill 0.71)
  Top 0.254: v80.48,64.13 75.4,69.21 IC4.10
  Bottom 0.254: R14.2 88.1,64.13 v80.48,64.13
N$56
  Bottom 0.254: C4.2 13.17,18.41 IC2.2
N$57
  Top 0.508: C4.1 X4.1
N$58
  Bottom 0.254: R17.2 71.59,18.41 67.78,14.6 IC5.3
N$59
  Bottom 0.254: R18.2 89.37,9.52 77.94,9.52 76.67,8.25 69.05,8.25 67.78,9.52 IC5.5
N$60
  Top 0.254: IC3.8 R24.2
  Bottom 0.254: IC3.5 67.78,36.19 72.86,31.11 IC3.8
N$61
  Top 0.254: C30.2 R11.3
N$62  (via drill 0.71)
  Top 0.254: R19.1 IC3.7 IC3.6 | v93.18,29.84 94.45,31.11 94.45,51.43 93.18,52.7 RN2.1
  Bottom 0.254: v93.18,29.84 69.05,29.84 67.78,31.11 IC3.7
N$72
  Bottom 0.254: R15.2 89.37,61.59 90.64,61.59 90.64,66.67 77.94,66.67 76.67,67.94 69.05,67.94 67.78,69.21 IC4.5
NINV1
  Top 0.254: IC1.1 C5.2
NINV2
  Top 0.254: C7.2 10.63,70.48 IC1.17
NINV3
  Top 0.254: IC2.17 C9.2
VCC
  Top 1.016: C34.+ R21.2 13.17,65.4 13.17,64.13 | IC1.13 C10.1 13.17,64.13 | IC2.13 C15.1 15.71,32.38 | C33.+ R20.2 15.71,32.38 | 15.71,31.11 15.71,26.03 11.9,22.22 IC2.5 | 15.71,31.11 15.71,32.38 | 14.44,59.05 14.44,62.86 13.17,64.13 | 14.44,59.05 14.44,55.24 IC1.5 | 14.44,59.05 24.6,59.05 24.6,43.81 23.33,42.54 23.33,38.73 15.71,31.11 | 30.95,8.25 C36.2 C35.+
  Bottom 1.016: IC2.5 25.87,22.22 27.14,23.49 43.65,23.49 43.65,19.68 30.95,6.98 C35.+ 28.41,5.71 D1.C
VCC/2
  Top 0.508: R15.1 R14.1 R13.1 R12.1 | IC6.2 IC6.1 | R3.1 80.48,60.32 R2.2 | R5.1 81.75,42.54 R23.2 81.75,26.03 | R22.1 R6.2 81.75,26.03 | 81.75,26.03 R10.1 R16.1 R17.1 R18.1 86.83,6.98 LSP3.MP
  Bottom 0.508: IC6.2 67.78,57.78 69.05,56.51 76.67,56.51 R3.1 84.29,57.78 R15.1 83.02,51.43 R5.1 | R11.1 62.7,42.54 69.05,42.54 69.05,36.19 70.32,36.19 71.59,34.92 80.48,34.92 R23.2
VDD  (via drill 0.71)
  Top 1.016: IC6.8 R1.2 | R7.2 LSP5.MP IC4.4 C40.2 69.05,71.75 v69.05,62.86 C43.2 69.05,38.73 | C38.2 56.35,8.25 C37.+ D3.C | IC5.4 C41.2 69.05,12.06 69.05,38.73 | IC3.4 C39.2 69.05,38.73
  Bottom 1.016: v69.05,62.86 70.32,62.86 72.86,60.32 IC6.8 | C38.2 61.43,10.79 62.7,10.79 63.97,12.06 IC5.4
WN1
  Top 0.254: IC4.2 IC4.1 | LSP4.MP 53.81,70.48 53.81,48.89 55.08,47.62 X1.1
  Bottom 0.254: LSP4.MP 63.97,78.1 65.24,76.83 IC4.2
WN2
  Top 0.254: IC4.13 IC4.14 72.86,79.37 72.86,80.64 61.43,80.64 51.27,70.48 51.27,41.27 58.89,41.27 58.89,43.81 57.62,45.08 X1.2
WN3  (via drill 0.71)
  Top 0.254: IC4.9 IC4.8 | v52.54,59.05 52.54,45.08 55.08,42.54 X1.3
  Bottom 0.254: v52.54,59.05 58.89,65.4 71.59,65.4 72.86,66.67 IC4.9
WN4
  Top 0.254: IC4.7 IC4.6
  Bottom 0.254: X1.4 57.62,40 60.16,42.54 60.16,55.24 58.89,56.51 58.89,64.13 IC4.7
WN5
  Top 0.254: IC5.14 IC5.13
  Bottom 0.254: X1.5 55.08,37.46 53.81,36.19 53.81,31.11 60.16,31.11 71.59,19.68 IC5.14
WN6
  Top 0.254: IC5.2 IC5.1 65.24,19.68 65.24,29.84 60.16,29.84 57.62,32.38 X1.7
WN7  (via drill 0.71)
  Top 0.254: IC5.8 IC5.9 75.4,6.98 76.67,8.25 76.67,26.03 v74.13,28.57
  Bottom 0.254: v74.13,28.57 63.97,28.57 63.97,32.38 62.7,33.65 58.89,33.65 57.62,34.92 X1.6
WN8
  Top 0.254: IC5.7 IC5.6 65.24,6.98 63.97,8.25 63.97,28.57 60.16,28.57 58.89,29.84 X1.8
WN+
  Top 0.254: R11.2 IC3.3
WN_FEEDBACK
  Top 0.254: IC3.2 IC3.1 65.24,46.35 C32.2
